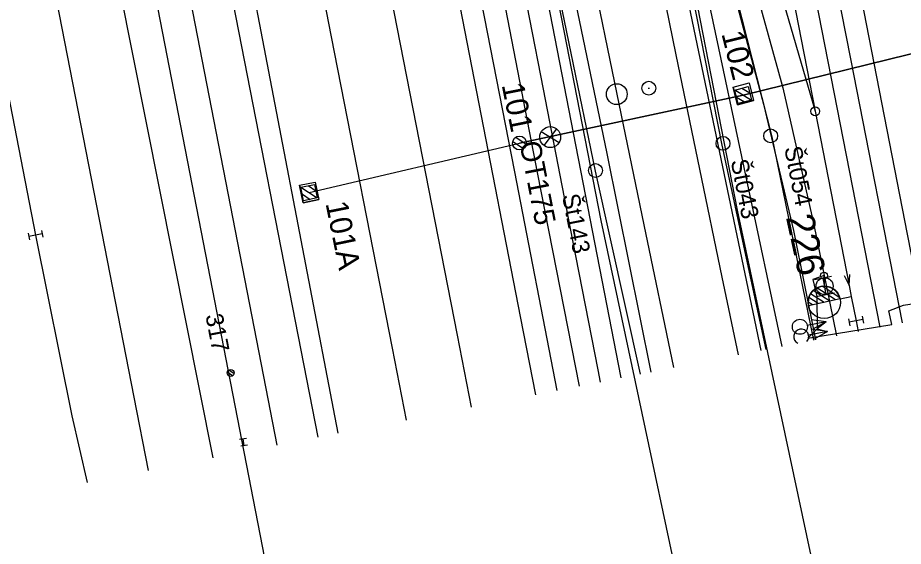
# Model space of a CAD drawing. Extents: x -545846 to -545044, y -1122650 to -1119108.
# Drawn here: x -545534.5 to -545470.6, y -1120392.1 to -1120354 of the extents above; entities that cross this region are included whole.
import ezdxf

# ---------------------------------------------------------------- set-up
doc = ezdxf.new("R2010")
doc.units = 0
for name, color, linetype in [('osvětlené plochy-hodnota-obrys', 7, 'Continuous'), ('Vrstva 1', 7, 'Continuous'), ('Vrstva 1 - Koleje', 7, 'Continuous'), ('Vrstva 11', 7, 'Continuous'), ('Vrstva 11 - Trakce', 7, 'Continuous'), ('Vrstva 12 - Trakce zaklady', 7, 'Continuous'), ('Vrstva 19 - Staniceni', 7, 'Continuous'), ('Vrstva 2 - Vyhybky', 7, 'Continuous'), ('Vrstva 25', 7, 'Continuous'), ('Vrstva 27', 7, 'Continuous'), ('Vrstva 28 - zabzar', 7, 'Continuous'), ('Vrstva 3', 7, 'Continuous'), ('Vrstva 3 - Lisy - Pocitaci body', 7, 'Continuous'), ('Vrstva 35', 7, 'Continuous'), ('Vrstva 4 - Teren - stezky - prechody - plochy', 7, 'Continuous'), ('Vrstva 43', 7, 'Continuous'), ('Vrstva 44', 7, 'Continuous'), ('Vrstva 7 - Namezniky-vystroj', 7, 'Continuous')]:
    doc.layers.add(name, color=color, linetype=linetype)

msp = doc.modelspace()

# ---------------------------------------------------------------- linework, layer by layer
at = {"layer": 'osvětlené plochy-hodnota-obrys'}
for points in [[(-545607.519, -1119727.517), (-545482.536, -1120367.871), (-545465.73, -1120446.743)], [(-545611.105, -1119760.367), (-545492.389, -1120368.615), (-545475.582, -1120447.487)], [(-545605.8, -1119934.355), (-545489.142, -1120534.587)]]:
    msp.add_lwpolyline(points, dxfattribs=at)
at = {"layer": 'Vrstva 1'}
for points in [[(-545484.065, -1120298.835), (-545481.72, -1120310.868), (-545477.659, -1120331.714), (-545474.512, -1120347.852), (-545470.27, -1120369.601), (-545469.079, -1120375.698)], [(-545512.079, -1120304.29), (-545509.652, -1120316.729), (-545504.92, -1120341.014), (-545501.351, -1120359.337), (-545498.197, -1120375.55), (-545497.107, -1120381.183)], [(-545516.751, -1120305.199), (-545515.098, -1120313.673), (-545510.162, -1120338.881), (-545507.312, -1120353.561), (-545502.757, -1120376.885), (-545501.739, -1120382.09)], [(-545530.725, -1120307.92), (-545525.484, -1120334.817), (-545521.174, -1120356.99), (-545516.72, -1120379.861), (-545515.757, -1120384.834)], [(-545521.096, -1120307.884), (-545519.375, -1120316.749), (-545514.88, -1120339.783), (-545511.839, -1120355.373), (-545507.449, -1120377.832), (-545506.438, -1120383.01)], [(-545540.046, -1120309.735), (-545537.636, -1120322.066), (-545534.947, -1120335.844), (-545532.811, -1120346.828), (-545526.072, -1120381.352), (-545525.038, -1120386.65)], [(-545544.711, -1120310.643), (-545542.3, -1120322.987), (-545539.581, -1120336.869), (-545536.549, -1120352.41), (-545533.181, -1120369.679), (-545530.563, -1120382.709), (-545529.441, -1120387.512)]]:
    msp.add_lwpolyline(points, dxfattribs=at)
at = {"layer": 'Vrstva 1 - Koleje'}
for points in [[(-545518.735, -1120170.873), (-545517.092, -1120179.279), (-545515.239, -1120188.8), (-545513.529, -1120197.566), (-545510.734, -1120211.886), (-545508.807, -1120221.766), (-545506.999, -1120231.05), (-545505.057, -1120241.005), (-545503.311, -1120249.961), (-545501.333, -1120260.123), (-545500.069, -1120266.614), (-545498.099, -1120276.734), (-545496.21, -1120286.398), (-545494.099, -1120296.551), (-545493.353, -1120299.814), (-545491.303, -1120308.782), (-545489.949, -1120314.331), (-545487.646, -1120323.268), (-545485.059, -1120332.675), (-545482.488, -1120341.567), (-545476.909, -1120360.737), (-545474.458, -1120373.309), (-545474.305, -1120374.094)], [(-545532.743, -1120173.486), (-545531.198, -1120181.414), (-545529.444, -1120190.408), (-545527.614, -1120199.79), (-545525.849, -1120208.859), (-545524.083, -1120217.878), (-545522.353, -1120226.804), (-545520.544, -1120236.067), (-545518.751, -1120245.244), (-545517.019, -1120254.134), (-545515.322, -1120262.818), (-545513.441, -1120272.491), (-545511.549, -1120282.172), (-545509.7, -1120291.668), (-545508.107, -1120299.843), (-545506.179, -1120309.724), (-545504.441, -1120318.636), (-545502.519, -1120328.489), (-545500.578, -1120338.445), (-545498.519, -1120349.006), (-545496.544, -1120359.143), (-545494.419, -1120370.064), (-545492.599, -1120379.398), (-545492.429, -1120380.268)], [(-545527.503, -1120175.582), (-545525.637, -1120185.143), (-545523.723, -1120194.953), (-545521.869, -1120204.454), (-545519.868, -1120214.706), (-545518.049, -1120224.023), (-545516.204, -1120233.485), (-545514.302, -1120243.235), (-545512.475, -1120252.605), (-545510.119, -1120264.679), (-545508.199, -1120274.552), (-545506.603, -1120282.757), (-545504.862, -1120291.702), (-545502.966, -1120301.337), (-545501.126, -1120310.611), (-545498.972, -1120321.418), (-545497.182, -1120330.346), (-545495.087, -1120340.689), (-545493.131, -1120350.244), (-545491.235, -1120359.489), (-545489.284, -1120368.922), (-545487.138, -1120379.232)], [(-545522.376, -1120177.035), (-545520.607, -1120186.115), (-545518.736, -1120195.699), (-545516.972, -1120204.753), (-545515.112, -1120214.314), (-545513.215, -1120224.036), (-545511.543, -1120232.598), (-545509.745, -1120241.825), (-545507.98, -1120250.879), (-545506.022, -1120260.921), (-545504.236, -1120270.098), (-545502.408, -1120279.461), (-545500.568, -1120288.895), (-545498.693, -1120298.415), (-545497.048, -1120306.715), (-545495.06, -1120316.74), (-545493.074, -1120326.625), (-545491.128, -1120336.251), (-545489.136, -1120346.042), (-545486.961, -1120356.657), (-545485.254, -1120364.907), (-545483.638, -1120372.702), (-545482.464, -1120378.318)], [(-545491.058, -1120287.923), (-545489.405, -1120296.386), (-545488.935, -1120298.789), (-545487.964, -1120303.745), (-545486.509, -1120311.24), (-545484.296, -1120322.688), (-545482.535, -1120331.849), (-545480.73, -1120341.135), (-545476.909, -1120360.737), (-545474.458, -1120373.309), (-545474.305, -1120374.094)], [(-545474.305, -1120374.094), (-545473.961, -1120375.862), (-545473.813, -1120376.624)]]:
    msp.add_lwpolyline(points, dxfattribs=at)
at = {"layer": 'Vrstva 11'}
for p, q in [((-545518.958, -1120379.819), (-545519.336, -1120379.563)), ((-545518.85, -1120379.666), (-545519.233, -1120379.406)), ((-545517.956, -1120384.334), (-545518.449, -1120384.413)), ((-545517.877, -1120384.827), (-545518.37, -1120384.906)), ((-545518.123, -1120384.867), (-545518.203, -1120384.373))]:
    msp.add_line(p, q, dxfattribs=at)
msp.add_circle((-545519.092, -1120379.61), 0.25, dxfattribs=at)
at = {"layer": 'Vrstva 11 - Trakce'}
for p, q in [((-545482.713, -1120359.199), (-545481.503, -1120359.923)), ((-545482.199, -1120359.07), (-545481.632, -1120359.409)), ((-545482.587, -1120359.711), (-545482.013, -1120360.054)), ((-545498.522, -1120362.611), (-545497.76, -1120363.115)), ((-545498.735, -1120362.919), (-545497.963, -1120363.431)), ((-545514.024, -1120366.207), (-545512.848, -1120366.986)), ((-545513.504, -1120366.101), (-545512.954, -1120366.466)), ((-545513.922, -1120366.724), (-545513.364, -1120367.093))]:
    msp.add_line(p, q, dxfattribs=at)
msp.add_lwpolyline([(-545513.437, -1120366.598), (-545498.25, -1120363.026), (-545482.109, -1120359.563), (-545461.191, -1120354.433), (-545443.985, -1120350.289)], dxfattribs=at)
for points in [[(-545481.746, -1120358.956), (-545481.502, -1120359.926), (-545482.472, -1120360.17), (-545482.716, -1120359.2)], [(-545513.046, -1120366.009), (-545512.848, -1120366.989), (-545513.828, -1120367.187), (-545514.026, -1120366.207)]]:
    msp.add_lwpolyline(points, close=True, dxfattribs=at)
msp.add_circle((-545498.25, -1120363.026), 0.5, dxfattribs=at)
at = {"layer": 'Vrstva 12 - Trakce zaklady'}
for p, q in [((-545482.838, -1120358.987), (-545481.674, -1120358.694)), ((-545482.518, -1120360.259), (-545481.354, -1120359.966)), ((-545514.12, -1120366.065), (-545513, -1120365.839)), ((-545513.859, -1120367.351), (-545512.729, -1120367.104))]:
    msp.add_line(p, q, dxfattribs=at)
for points in [[(-545482.518, -1120360.259), (-545482.838, -1120358.987), (-545481.674, -1120358.694), (-545481.354, -1120359.966), (-545482.518, -1120360.259)], [(-545481.674, -1120358.694), (-545481.674, -1120358.694), (-545481.354, -1120359.966), (-545481.354, -1120359.966)], [(-545482.838, -1120358.987), (-545482.838, -1120358.987), (-545482.518, -1120360.259), (-545482.518, -1120360.259)], [(-545514.12, -1120366.065), (-545513, -1120365.839), (-545512.729, -1120367.104), (-545513.859, -1120367.351), (-545514.12, -1120366.065)], [(-545514.12, -1120366.065), (-545514.12, -1120366.065), (-545513.859, -1120367.351), (-545513.859, -1120367.351)], [(-545513, -1120365.839), (-545513, -1120365.839), (-545512.729, -1120367.104), (-545512.729, -1120367.104)]]:
    msp.add_lwpolyline(points, dxfattribs=at)
at = {"layer": 'Vrstva 19 - Staniceni'}
msp.add_circle((-545491.232, -1120359.501), 0.75, dxfattribs=at)
at = {"layer": 'Vrstva 2 - Vyhybky'}
for p, q in [((-545475.441, -1120374.344), (-545476.786, -1120373.48)), ((-545475.134, -1120374.185), (-545476.412, -1120373.364)), ((-545476.271, -1120374.524), (-545477.243, -1120373.9)), ((-545475.855, -1120374.434), (-545477.051, -1120373.667)), ((-545475.108, -1120374.271), (-545474.305, -1120374.094)), ((-545477.1, -1120374.705), (-545477.421, -1120374.499)), ((-545475.109, -1120374.272), (-545477.397, -1120374.77)), ((-545476.685, -1120374.614), (-545477.368, -1120374.175)), ((-545475.109, -1120374.271), (-545475.109, -1120374.272))]:
    msp.add_line(p, q, dxfattribs=at)
for points in [[(-545480.73, -1120341.135), (-545476.909, -1120360.737), (-545474.458, -1120373.309), (-545474.305, -1120374.094)], [(-545482.488, -1120341.567), (-545476.909, -1120360.737)], [(-545474.809, -1120372.59), (-545474.458, -1120373.309), (-545474.403, -1120372.511)]]:
    msp.add_lwpolyline(points, dxfattribs=at)
for centre, radius in [((-545476.909, -1120360.737), 0.32), ((-545476.259, -1120374.521), 1.17)]:
    msp.add_circle(centre, radius, dxfattribs=at)
msp.add_arc((-545476.253, -1120374.521), 1.171, 12.31614, 192.27699, dxfattribs=at)
at = {"layer": 'Vrstva 25'}
for p, q in [((-545495.399, -1120363), (-545496.682, -1120362.208)), ((-545495.578, -1120362.001), (-545496.492, -1120363.199)), ((-545496.778, -1120362.74), (-545498.25, -1120363.026))]:
    msp.add_line(p, q, dxfattribs=at)
msp.add_lwpolyline([(-545461.191, -1120354.433), (-545482.109, -1120359.563), (-545498.25, -1120363.026)], dxfattribs=at)
msp.add_circle((-545496.037, -1120362.598), 0.754, dxfattribs=at)
at = {"layer": 'Vrstva 27'}
msp.add_line((-545476.265, -1120372.615), (-545476.275, -1120372.565), dxfattribs=at)
msp.add_circle((-545476.27, -1120372.59), 0.25, dxfattribs=at)
at = {"layer": 'Vrstva 28 - zabzar'}
for points in [[(-545476.23, -1120373.35), (-545476.27, -1120372.59), (-545477.07, -1120372.87), (-545476.79, -1120374.1), (-545476.78, -1120376.42), (-545477.44, -1120377.11), (-545471.37, -1120376.13), (-545471.59, -1120375.14), (-545470.55, -1120374.72), (-545467.76, -1120374.29), (-545465.72, -1120374.24), (-545463.06, -1120373.77), (-545462.26, -1120373.53)], [(-545476.13, -1120375.92), (-545476.78, -1120376.42), (-545476.03, -1120376.63)]]:
    msp.add_lwpolyline(points, dxfattribs=at)
at = {"layer": 'Vrstva 3'}
for p, q in [((-545533.72, -1120369.529), (-545533.624, -1120370.02)), ((-545532.69, -1120369.583), (-545533.672, -1120369.775)), ((-545532.738, -1120369.338), (-545532.642, -1120369.829))]:
    msp.add_line(p, q, dxfattribs=at)
at = {"layer": 'Vrstva 3 - Lisy - Pocitaci body'}
for p, q in [((-545476.952, -1120372.863), (-545475.743, -1120372.628)), ((-545476.112, -1120373.955), (-545476.348, -1120372.745)), ((-545476.717, -1120374.072), (-545475.508, -1120373.837)), ((-545476.13, -1120375.92), (-545477.485, -1120376.183)), ((-545476.13, -1120375.92), (-545477.212, -1120375.779)), ((-545476.13, -1120375.92), (-545477.08, -1120376.456)), ((-545474.5, -1120375.712), (-545474.404, -1120376.203)), ((-545473.47, -1120375.766), (-545474.452, -1120375.958)), ((-545473.518, -1120375.521), (-545473.422, -1120376.012)), ((-545476.03, -1120376.63), (-545477.385, -1120376.893)), ((-545476.03, -1120376.63), (-545477.112, -1120376.489)), ((-545476.03, -1120376.63), (-545476.98, -1120377.166))]:
    msp.add_line(p, q, dxfattribs=at)
for centre, radius in [((-545476.231, -1120373.348), 0.616), ((-545478.017, -1120376.285), 0.542)]:
    msp.add_circle(centre, radius, dxfattribs=at)
msp.add_arc((-545477.917, -1120376.995), 0.542, 319.51993, 242.62747, dxfattribs=at)
at = {"layer": 'Vrstva 35'}
for points in [[(-545512.782, -1120384.251), (-545519.924, -1120347.678)], [(-545511.33, -1120383.967), (-545518.345, -1120347.435)]]:
    msp.add_lwpolyline(points, dxfattribs=at)
at = {"layer": 'Vrstva 4 - Teren - stezky - prechody - plochy'}
for points in [[(-545627.289, -1119622.488), (-545623.041, -1119643.798), (-545614.848, -1119686.378), (-545604.257, -1119740.381), (-545596.077, -1119782.585), (-545587.168, -1119828.353), (-545576.202, -1119884.317), (-545565.971, -1119936.976), (-545553.74, -1119999.834), (-545541.535, -1120062.236), (-545531.079, -1120116.013), (-545520.819, -1120168.515), (-545508.831, -1120230.344), (-545499.12, -1120279.845), (-545497.248, -1120289.164), (-545495.162, -1120299.078), (-545493.408, -1120306.853), (-545489.261, -1120323.659), (-545486.768, -1120332.638), (-545482.019, -1120349.033), (-545479.258, -1120359.037), (-545477.044, -1120368.814), (-545475.362, -1120376.928)], [(-545628.853, -1119622.763), (-545624.686, -1119644.063), (-545616.354, -1119686.873), (-545605.869, -1119740.58), (-545597.619, -1119782.547), (-545588.666, -1119828.365), (-545577.778, -1119884.555), (-545567.555, -1119936.921), (-545555.278, -1120000.024), (-545543.118, -1120062.357), (-545532.633, -1120116.151), (-545522.436, -1120168.075), (-545510.345, -1120230.332), (-545500.633, -1120280.001), (-545495.304, -1120307.199), (-545490.342, -1120331.504), (-545485.9, -1120353.688), (-545480.839, -1120378)], [(-545488.754, -1120379.549), (-545491.925, -1120363.788), (-545496.278, -1120342.782), (-545500.506, -1120321.731), (-545508.599, -1120280.828), (-545518.82, -1120228.621), (-545531.029, -1120165.923), (-545540.626, -1120116.248), (-545552.245, -1120057.042), (-545557.488, -1120030.03), (-545563.439, -1119999.512), (-545572.128, -1119954.79), (-545581.61, -1119906.246), (-545591.458, -1119855.639), (-545600.962, -1119806.943), (-545610.434, -1119758.233), (-545616.648, -1119726.461), (-545621.696, -1119701.088), (-545622.533, -1119696.196), (-545623.462, -1119696.331)], [(-545490.916, -1120379.972), (-545493.99, -1120364.147), (-545502.163, -1120322.09), (-545510.164, -1120281.035), (-545520.235, -1120229.023), (-545532.517, -1120166.017), (-545542.296, -1120116.028), (-545553.809, -1120057.082), (-545558.932, -1120030.597), (-545564.969, -1119999.794), (-545573.753, -1119955.036), (-545583.127, -1119906.578), (-545593.017, -1119855.856), (-545602.553, -1119806.891), (-545612.123, -1119758.671), (-545618.333, -1119726.047), (-545620.676, -1119713.873), (-545622.612, -1119701.558), (-545623.462, -1119696.331)], [(-545495.535, -1120380.876), (-545498.596, -1120365.093), (-545507.092, -1120321.572), (-545515.017, -1120281.173), (-545524.994, -1120229.535), (-545536.771, -1120169.47), (-545546.676, -1120118.787), (-545557.312, -1120064.079), (-545563.312, -1120033.308), (-545569.884, -1119999.645), (-545578.452, -1119955.82), (-545587.921, -1119907.338), (-545597.812, -1119856.591), (-545607.33, -1119807.681), (-545610.119, -1119793.19), (-545611.535, -1119784.447), (-545612.6, -1119777.287), (-545613.018, -1119774.47), (-545612.047, -1119774.376)], [(-545493.924, -1120380.561), (-545496.951, -1120365.161), (-545505.376, -1120321.611), (-545513.278, -1120281.443), (-545523.478, -1120229.493), (-545535.102, -1120169.56), (-545545.054, -1120118.579), (-545554.55, -1120069.937), (-545561.701, -1120033.181), (-545568.213, -1119999.317), (-545576.806, -1119955.508), (-545586.262, -1119907.136), (-545605.677, -1119807.326), (-545612.047, -1119774.376)], [(-545480.19, -1120327.425), (-545474.356, -1120356.955), (-545470.624, -1120376)], [(-545481.74, -1120327.759), (-545475.994, -1120357.133), (-545472.25, -1120376.318)], [(-545488.716, -1120331.415), (-545488.2, -1120332.717), (-545483.361, -1120350.001), (-545480.647, -1120360.215), (-545478.471, -1120369.339), (-545476.879, -1120377.224)], [(-545488.716, -1120331.415), (-545488.577, -1120332.696), (-545484.459, -1120353.475), (-545479.322, -1120377.703)]]:
    msp.add_lwpolyline(points, dxfattribs=at)
at = {"layer": 'Vrstva 43'}
for centre in [(-545483.564, -1120363.05), (-545480.128, -1120362.512), (-545492.769, -1120365.014)]:
    msp.add_circle(centre, 0.5, dxfattribs=at)
at = {"layer": 'Vrstva 44'}
for points in [[(-545629.268, -1120065.402), (-545629.634, -1120087.876), (-545630.039, -1120112.736), (-545629.044, -1120137.319), (-545628.839, -1120137.845), (-545628.579, -1120138.408), (-545605.178, -1120154.045), (-545604.485, -1120154.235), (-545603.868, -1120154.242), (-545567.82, -1120146.847), (-545567.035, -1120147.195), (-545566.786, -1120147.869), (-545557.769, -1120194.412), (-545548.548, -1120241.228), (-545548.384, -1120241.623), (-545548.361, -1120241.936), (-545539.222, -1120288.885), (-545539.174, -1120289.236), (-545530.2, -1120336.386), (-545530.153, -1120336.813), (-545530.009, -1120337.37), (-545520.393, -1120385.741)], [(-545480.443, -1120377.922), (-545483.628, -1120363.18), (-545490.393, -1120328.833), (-545490.4, -1120328.688)], [(-545477.006, -1120377.249), (-545480.026, -1120362.567), (-545488.706, -1120328.407)], [(-545489.516, -1120379.698), (-545492.775, -1120365.061), (-545499.794, -1120330.975), (-545499.82, -1120330.883)]]:
    msp.add_lwpolyline(points, dxfattribs=at)
at = {"layer": 'Vrstva 7 - Namezniky-vystroj'}
msp.add_line((-545488.972, -1120359.073), (-545488.872, -1120359.073), dxfattribs=at)
msp.add_circle((-545488.922, -1120359.073), 0.5, dxfattribs=at)

# ---------------------------------------------------------------- texts
at = {"layer": 'Vrstva 11'}
msp.add_text('317', height=1.25, rotation=280.86461, dxfattribs=at).set_placement((-545520.922, -1120375.461))
at = {"layer": 'Vrstva 11 - Trakce'}
for s, rotation, p in [('102', 284.121, (-545483.688, -1120355.137)), ('101', 281.47263, (-545499.544, -1120358.83)), ('101A', 281.47263, (-545512.258, -1120367.379))]:
    msp.add_text(s, height=1.6, rotation=rotation, dxfattribs=at).set_placement(p)
at = {"layer": 'Vrstva 2 - Vyhybky'}
msp.add_text('226', height=2, rotation=282.29657, dxfattribs=at).set_placement((-545479.032, -1120368.369))
at = {"layer": 'Vrstva 25'}
msp.add_text('OT175', height=1.5, rotation=281.01098, dxfattribs=at).set_placement((-545498.25, -1120363.026))
at = {"layer": 'Vrstva 43'}
for s, p in [('Št054', (-545479.147, -1120363.372)), ('Št043', (-545483.013, -1120364.306)), ('Št143', (-545495.184, -1120366.803))]:
    msp.add_text(s, height=1.25, rotation=280.99979, dxfattribs=at).set_placement(p)

doc.saveas('drawing.dxf')
